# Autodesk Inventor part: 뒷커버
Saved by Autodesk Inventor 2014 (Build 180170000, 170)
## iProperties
Created: 2024-08
Part Number: 뒷커버
Material: 일반
Document SubType Name: Modeling
Designer: dg
Density: 1 g/cm^3
Appearance: 기본값
Author: dg
Author: jhkim
Creation Date: 2024-08-09
Sending System: Autodesk Inventor 2025
Preprocessor: ST-DEVELOPER v20
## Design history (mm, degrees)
node "뒷커버1"
node "솔리드1"
node "기준1"
